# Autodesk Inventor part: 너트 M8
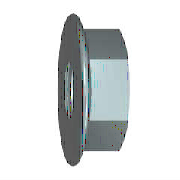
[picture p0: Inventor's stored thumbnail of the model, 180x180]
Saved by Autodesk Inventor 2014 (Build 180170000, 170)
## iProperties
Created: 2015-09
Part Number: 너트 M8
Material: 스테인리스강
Description: 플랜지붙이 6각 너트 - 일반 스레드
Document SubType Name: Modeling
Standard: ISO 4161
Designer: mduedu
Standard Revision: 2판 1999-03-15
Standards Organization: ISO
Language: ko-KR
Size Designation: M8
Categories: <MemberInstance><Categories><Category DisplayName="조임쇠" InternalName="e4da775c-781d-43d5-af7c-5136215cf5a6" Mnemonic="FSTN"><Category DisplayName="너트" InternalN
Density: 8.08 g/cm^3
Appearance: 기본값
Author: mduedu
IsCustomPart: 1
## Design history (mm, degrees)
sketch "스케치1"
  geometry: L1 (-1.844, 0)-(9.641, 0) reference; L2 (3.107, 6.5)-(2.288, 8.257); L3 (3.107, 6.5)-(8, 6.5); L4 (8, 6.5)-(8, 0); L5 (3.107, 6.5)-(3.107, 0); L6 (0, -1.835)-(0, 11.01) reference; A1 r 1.2 centre (1.2, 7.75) between (2.288, 8.257) and (0, 7.75); 1 further point
  constraints: 8 end point, 3 point on line, 2 perpendicular, 2 point on circle, 2 tangent, 1 centre point, 1 parallel
  dimensions: "d2" = 13 diameter of L3 L1 (= SW); "d4" = 17.9 dimension on A1 L1 (= LADI); "d5" = 1.2 radius of A1 (= PHH); "d15" = 8 distance between parallel lines of L4 L6 (= KOH); "d16" = 25 deg angle of L6 L2 (= KEWI)
revolve "링" sketch "스케치1" stored, may be unused: angle "d8" = 90 deg
sketch "스케치2"
  geometry: L1 (-6.5, -3.753)-(-6.5, 3.753); L2 (-6.5, 3.753)-(0, 7.506); L3 (0, 7.506)-(6.5, 3.753); L4 (6.5, 3.753)-(6.5, -3.753); L5 (6.5, -3.753)-(0, -7.506); L6 (0, -7.506)-(-6.5, -3.753); C1 r 4.9 at (0, 0); C2 r 7.75 at (0, 0) reference; 1 further point
  constraints: 12 end point, 1 centre point, 1 coincident, 1 vertical, 11 other
  dimensions: "d6" = 15.01111 distance of L5.end L2.end (= 1.1547 x SW)
extrude "본체" join sketch "스케치2" distance "d7" = 8 (= KOH); taper "d9" = 0 deg
sketch "스케치3"
  geometry: L1 (2.638, 7.506)-(8, 7.506) reference; L2 (8, 3.753)-(8, 7.506) reference; L3 (0, -7.75)-(0, 7.75) reference; L4 (-1.6, 0)-(9.6, 0) reference; L5 (7.419, 7.506)-(8, 6.5)
  constraints: 2 end point, 2 point on line
  dimensions: "d10" = 30 deg angle of L2 L5 (= ANG1); "d11" = 13 diameter of L5.end L4 (= SW0)
revolve "모따기1" sketch "스케치3" stored, may be unused: angle "d24" = 90 deg
sketch "스케치4"
  geometry: C1 r 7.75 at (0, 0) reference; 1 further point
  constraints: 1 coincident
hole "스레드" sketch "스케치4" at (0, 0) diameter "d25" = 6.647; stored, may be unused: countersink angle "d29" = 82 deg, drill point angle "d31" = 118 deg; dims "d26" = 6, "d27" = 4, "d28" = 2, "d30" = 8
workaxis "Work Axis1"
workplane "Work Plane1"
body "Solid1"
chamfer "모따기2" distance "d12" = 0.67658 (= -0.5 x GD1 + 0.5 x NND); stored, may be unused: angle "d13" = 30 deg, second distance "d46" = 0.67658 (= -0.5 x GD1 + 0.5 x NND)
chamfer "모따기3" distance "d51" = 0.67658 (= -0.5 x GD1 + 0.5 x NND); stored, may be unused: second distance "d52" = 2, angle "d53" = 45 deg
other parameters: "ANG1" = 30 deg [user parameter; used in 1 equation term], "KEWI" = 25 deg [user parameter; used in 1 equation term], "NND" = 8 [user parameter; used in 4 equation terms], "LADI" = 17.9 [user parameter; used in 2 equation terms], "SW" = 13 [user parameter; used in 3 equation terms], "PHH" = 1.2 [user parameter; used in 3 equation terms], "KOH" = 8 (= NND) [user parameter; used in 2 equation terms], "SW0" = 13 [user parameter; used in 1 equation term], "GD1" = 6.64684 (computed from THREADDIA, PTC, TOA) [user parameter; used in 3 equation terms], "d1" = 17.9 (= LADI), "d3" = 1.2 (= PHH), "d45" = 0, "d47" = 0, "d49" = 0, "d54" = 0, "GUL" = 0.67658 (= 0.541266 x PTC) [user parameter], "TPU" = 8 (computed from PTC) [user parameter], "RR" = 1.2 (= PHH) [user parameter], "THREADDIA" = 8 [user parameter; used in 1 equation term], "TOA" = 30 deg [user parameter; used in 1 equation term], "PTC" = 1.25 [user parameter; used in 4 equation terms], "GAL" = 0.67658 (= 0.541266 x PTC) [user parameter], "E0" = 15.015 (= 1.155 x SW) [user parameter]
